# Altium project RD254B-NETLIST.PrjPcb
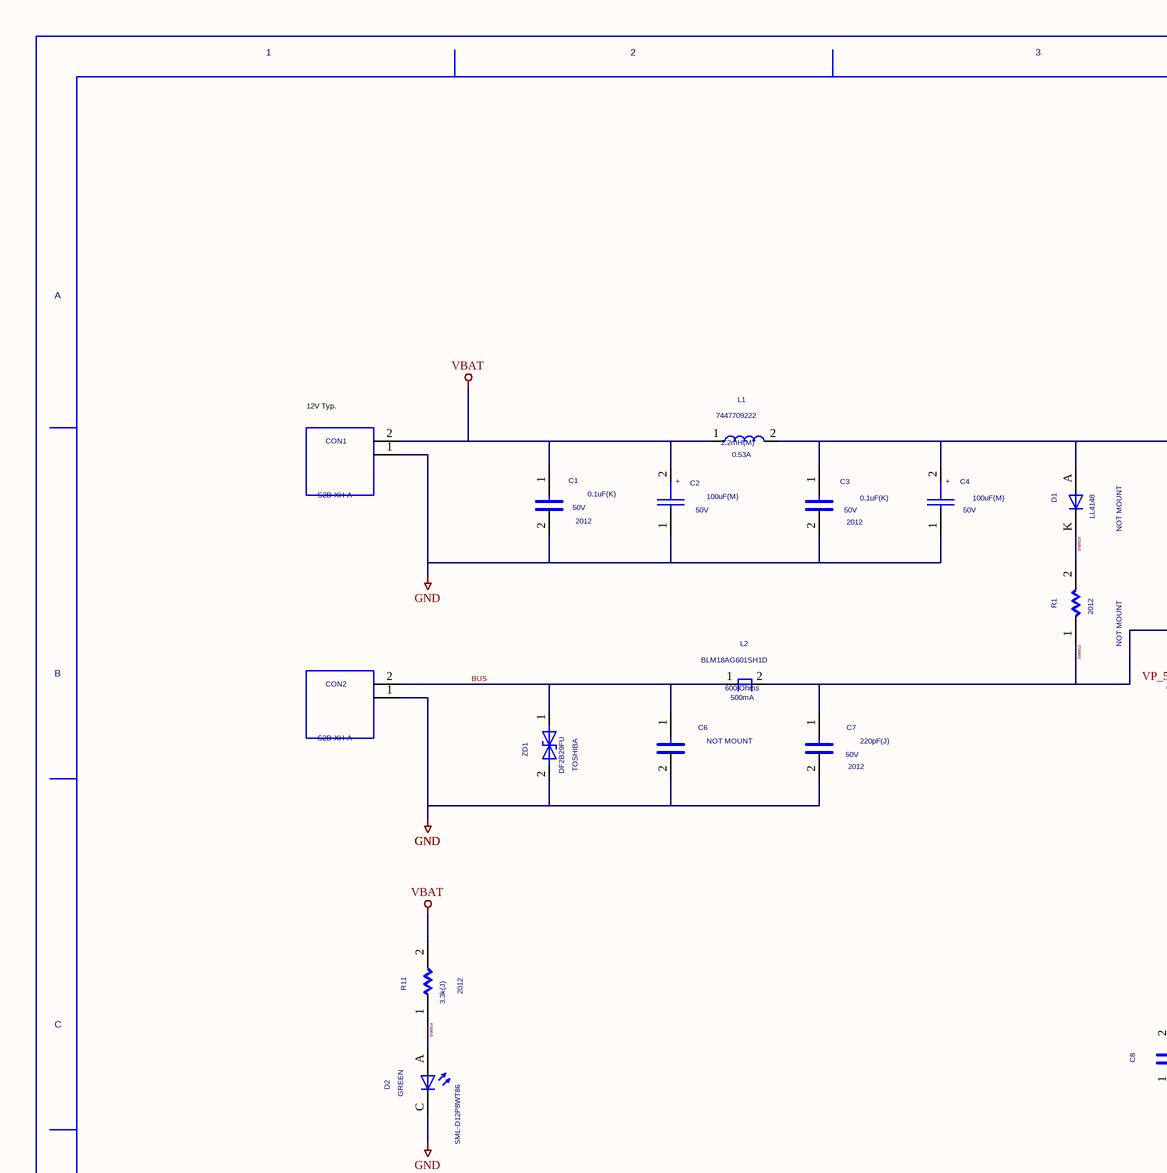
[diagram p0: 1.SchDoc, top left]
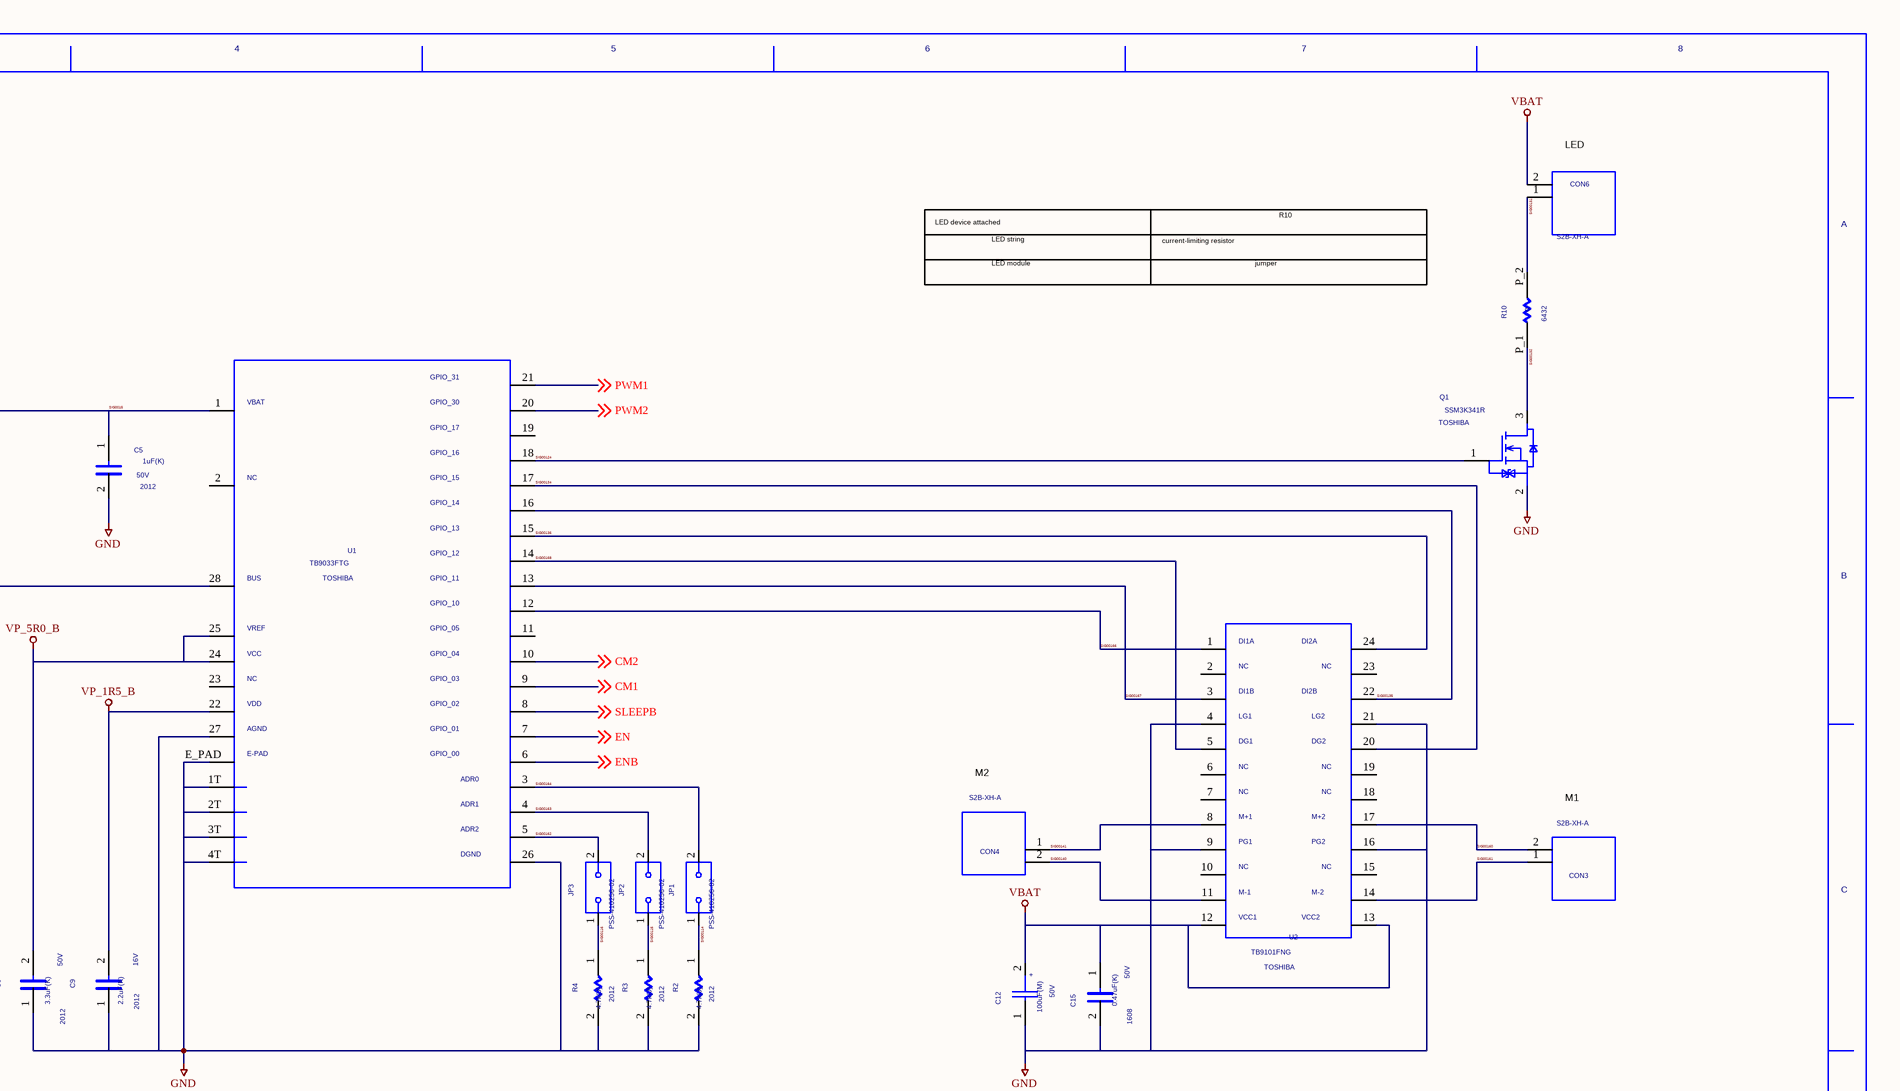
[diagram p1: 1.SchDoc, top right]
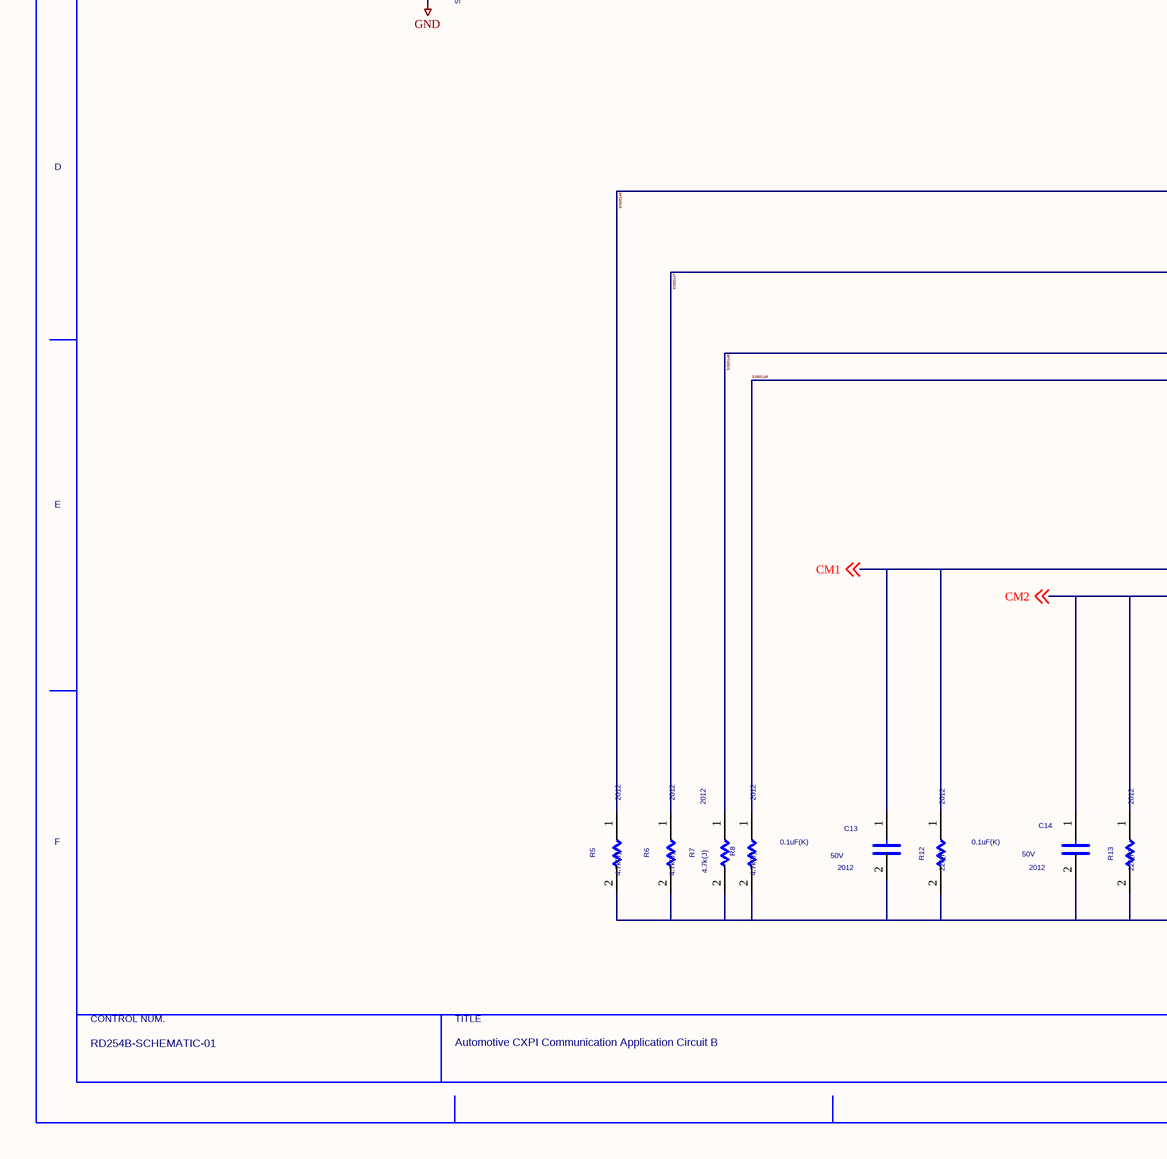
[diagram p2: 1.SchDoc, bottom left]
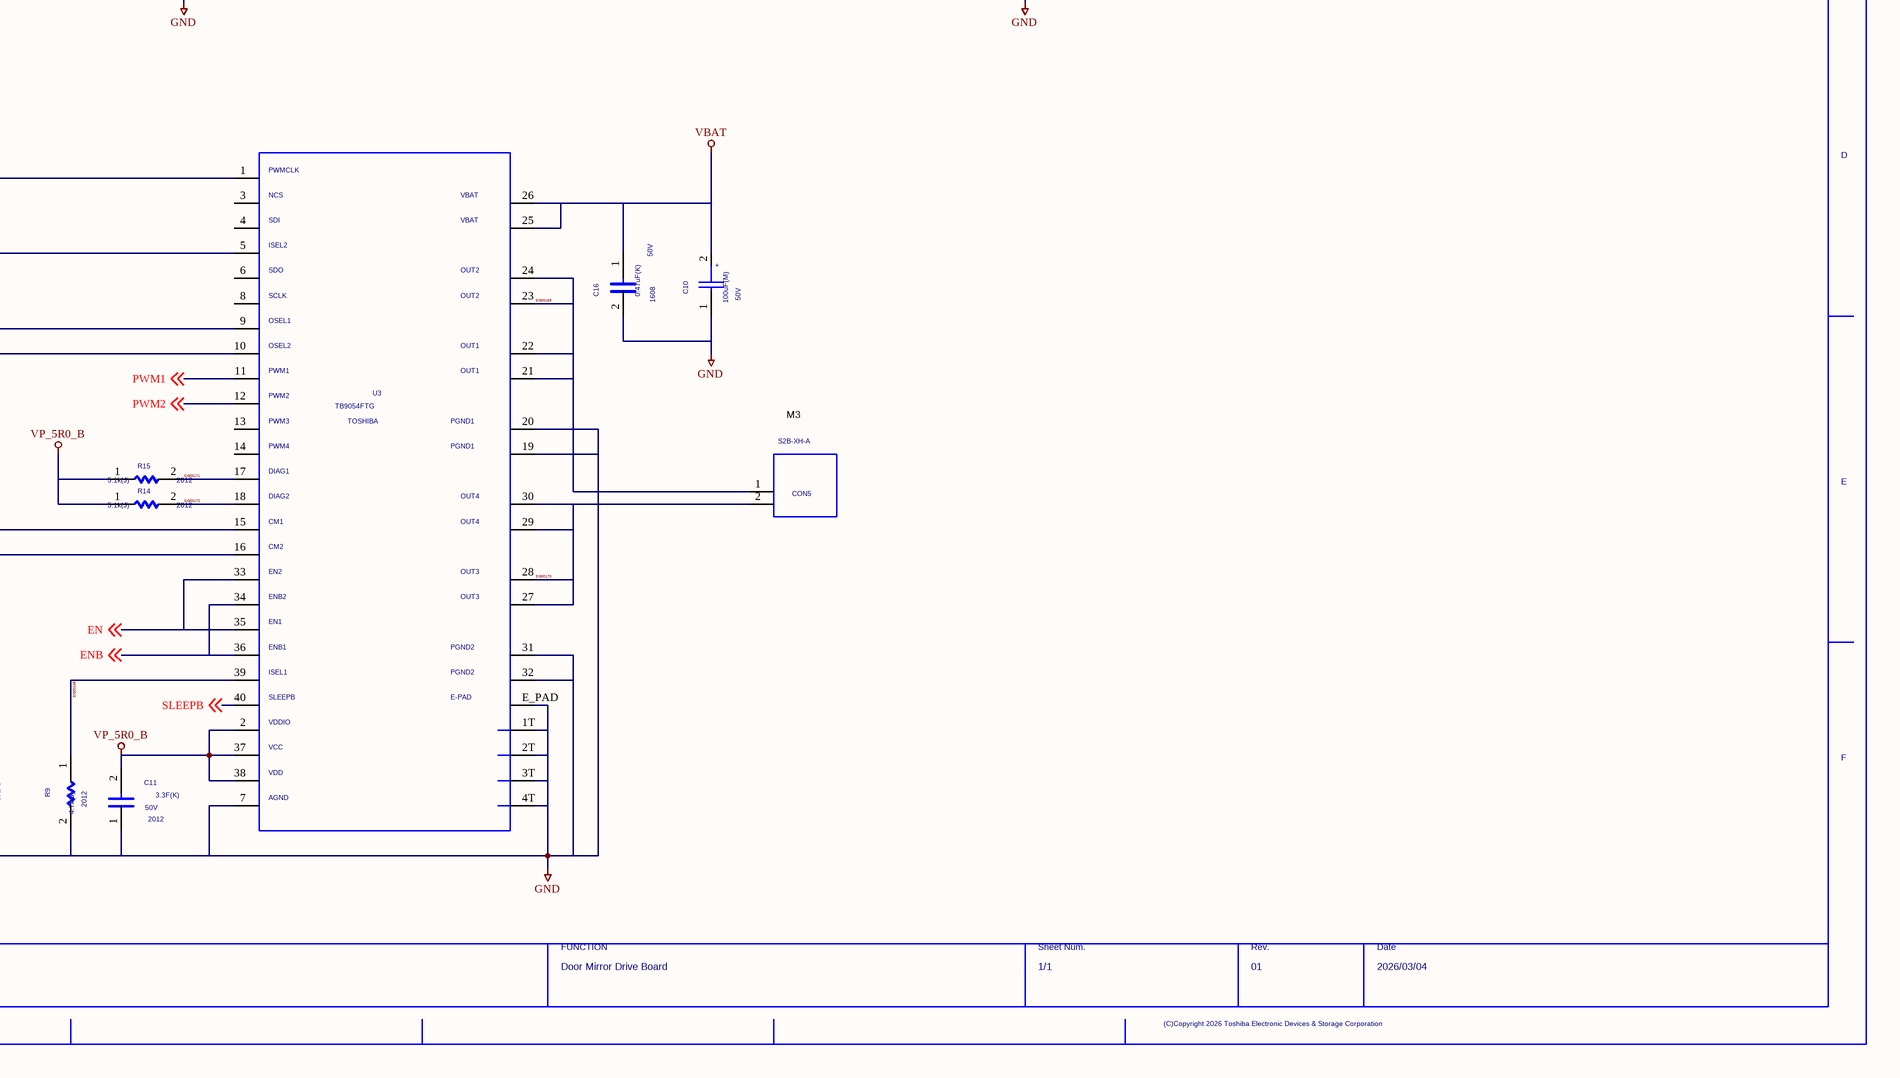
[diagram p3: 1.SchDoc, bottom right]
1 sheet, 50 parts. Net scope: global (net labels, ports and power ports of the same name join across sheets).

## Sheet 1.SchDoc
size 609 x 444 mm

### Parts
C1  VAL1: 0.1uF(K)  VAL2: 50V  SIZECODESMD: 2012  (hidden comment: C)
C2  VAL1: 100uF(M)  VAL2: 50V  (hidden comment: CP)
C3  VAL1: 0.1uF(K)  VAL2: 50V  SIZECODESMD: 2012  (hidden comment: C)
C4  VAL1: 100uF(M)  VAL2: 50V  (hidden comment: CP)
C5  VAL1: 1uF(K)  VAL2: 50V  SIZECODESMD: 2012  (hidden comment: C)
C6  NOTMOUNT: NOT MOUNT  (hidden comment: C)
C7  VAL1: 220pF(J)  VAL2: 50V  SIZECODESMD: 2012  (hidden comment: C)
C8  VAL1: 3.3uF(K)  VAL2: 50V  SIZECODESMD: 2012  (hidden comment: C)
C9  VAL1: 2.2uF(K)  VAL2: 16V  SIZECODESMD: 2012  (hidden comment: C)
C10  VAL1: 100uF(M)  VAL2: 50V  (hidden comment: CP)
C11  VAL1: 3.3F(K)  VAL2: 50V  SIZECODESMD: 2012  (hidden comment: C)
C12  VAL1: 100uF(M)  VAL2: 50V  (hidden comment: CP)
C13  VAL1: 0.1uF(K)  VAL2: 50V  SIZECODESMD: 2012  (hidden comment: C)
C14  VAL1: 0.1uF(K)  VAL2: 50V  SIZECODESMD: 2012  (hidden comment: C)
C15  VAL1: 0.47uF(K)  VAL2: 50V  SIZECODESMD: 1608  (hidden comment: C)
C16  VAL1: 0.47uF(K)  VAL2: 50V  SIZECODESMD: 1608  (hidden comment: C)
CON1  S2B-XH-A
CON2  S2B-XH-A
CON3  S2B-XH-A
CON4  S2B-XH-A
CON5  S2B-XH-A
CON6  S2B-XH-A
D1  NOTMOUNT: NOT MOUNT  VAL3: LL4148  (hidden comment: D)
D2  VAL2: GREEN  VAL3: SML-D12P8WT86  (hidden comment: LED)
JP1  PSS-410256-02
JP2  PSS-410256-02
JP3  PSS-410256-02
L1  VAL1: 2.2mH(M)  VAL2: 0.53A  VAL3: 7447709222  (hidden comment: L)
L2  VAL2: 500mA  VAL1: 600 Ohms  VAL3: BLM18AG601SH1D  (hidden comment: FB)
Q1  USERCOMPTEXT3: TOSHIBA  (hidden comment: SSM3K341R)
R1  NOTMOUNT: NOT MOUNT  SIZECODESMD: 2012  (hidden comment: R)
R2  VAL1: 4.7k(J)  SIZECODESMD: 2012  (hidden comment: R)
R3  VAL1: 4.7k(J)  SIZECODESMD: 2012  (hidden comment: R)
R4  VAL1: 4.7k(J)  SIZECODESMD: 2012  (hidden comment: R)
R5  VAL1: 4.7k(J)  SIZECODESMD: 2012  (hidden comment: R)
R6  VAL1: 4.7k(J)  SIZECODESMD: 2012  (hidden comment: R)
R7  VAL1: 4.7k(J)  SIZECODESMD: 2012  (hidden comment: R)
R8  VAL1: 4.7k(J)  SIZECODESMD: 2012  (hidden comment: R)
R9  VAL1: 4.7k(J)  SIZECODESMD: 2012  (hidden comment: R)
R10  VAL1: 0  SIZECODESMD: 6432  (hidden comment: R)
R11  VAL1: 3.3k(J)  SIZECODESMD: 2012  (hidden comment: R)
R12  VAL1: 220(F)  SIZECODESMD: 2012  (hidden comment: R)
R13  VAL1: 220(F)  SIZECODESMD: 2012  (hidden comment: R)
R14  VAL1: 5.1k(J)  SIZECODESMD: 2012  (hidden comment: R)
R15  VAL1: 5.1k(J)  SIZECODESMD: 2012  (hidden comment: R)
U1  VAL3: TB9033FTG  USERCOMPTEXT3: TOSHIBA  (hidden comment: TB9033FTGIC_VERB)
U2  USERCOMPTEXT3: TOSHIBA  (hidden comment: TB9101FNG)
U3  VAL3: TB9054FTG  USERCOMPTEXT3: TOSHIBA  (hidden comment: TB9054FTG_VERB)
U?  DATE: 2026/03/04  DRAWINGNUMBER: RD254B-SCHEMATIC-01  TITLE: Automotive CXPI Communication Application Circuit B  FUNCTION: Door Mirror Drive Board  SHEETNUMBER: 1/1  REVISION: 01  (hidden comment: WAKU_DEF_A3_1)
ZD1  USERCOMPTEXT3: TOSHIBA  VAL3: DF2B29FU  (hidden comment: ZDB)

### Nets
GND: C1.2 C2.1 C3.2 C4.1 C5.2 C6.2 C7.2 C8.1 C9.1 C10.1 C11.1 C12.1 C13.2 C14.2 C15.2 C16.2 CON1.1 CON2.1 D2.C Q1.2 R2.2 R3.2 R4.2 R5.2 R6.2 R7.2 R8.2 R9.2 R12.2 R13.2 U1.1T U1.2T U1.3T U1.4T U1.26 U1.27 U1.E_PAD U2.4 U2.9 U2.16 U2.21 U3.1T U3.2T U3.3T U3.4T U3.7 U3.19 U3.20 U3.31 U3.32 U3.E_PAD ZD1.2
VBAT: C1.1 C2.2 C10.2 C12.2 C15.1 C16.1 CON1.2 CON6.2 L1.1 R11.2 U2.12 U2.13 U3.25 U3.26
VP_1R5_B: C9.2 U1.22
VP_5R0_B: C8.2 C11.2 R14.1 R15.1 U1.24 U1.25 U3.2 U3.37 U3.38
BUS: C6.1 CON2.2 L2.1 ZD1.1
CM1: C13.1 R12.1 U1.9 U3.15 ; off-sheet CM1
CM2: C14.1 R13.1 U1.10 U3.16 ; off-sheet CM2
EN: U1.7 U3.33 U3.35 ; off-sheet EN
ENB: U1.6 U3.34 U3.36 ; off-sheet ENB
PWM1: U1.21 U3.11 ; off-sheet PWM1
PWM2: U1.20 U3.12 ; off-sheet PWM2
SIG0012: C7.1 L2.2 R1.1 U1.28
SIG0013: D1.K(C) R1.2
SIG0014: D2.A R11.1
SIG0015: C3.1 C4.2 C5.1 D1.A L1.2 U1.1
SIG00114: JP1.1 R2.1
SIG00115: JP2.1 R3.1
SIG00116: JP3.1 R4.1
SIG00124: Q1.1 U1.18
SIG00131: CON6.1 R10.P_2
SIG00132: Q1.3 R10.P_1
SIG00134: U1.17 U2.20
SIG00135: U1.16 U2.22
SIG00136: U1.15 U2.24
SIG00140: CON4.2 U2.11
SIG00141: CON4.1 U2.8
SIG00145: R9.1 U3.39
SIG00146: R5.1 U3.1
SIG00147: R6.1 U3.5
SIG00148: R7.1 U3.9
SIG00149: R8.1 U3.10
SIG00160: CON3.2 U2.17
SIG00161: CON3.1 U2.14
SIG00162: JP3.2 U1.5
SIG00163: JP2.2 U1.4
SIG00164: JP1.2 U1.3
SIG00166: U1.12 U2.1
SIG00167: U1.13 U2.3
SIG00168: U1.14 U2.5
SIG00169: CON5.1 U3.21 U3.22 U3.23 U3.24
SIG00170: CON5.2 U3.27 U3.28 U3.29 U3.30
SIG00171: R15.2 U3.17
SIG00172: R14.2 U3.18
SLEEPB: U1.8 U3.40 ; off-sheet SLEEPB

Not connected (* = marked no-connect by the designer): U1 2 11 19 23; U2 2 6 7 10 15 18 19 23; U3 3 4 6 8 13 14

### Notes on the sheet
- (near CON6) LED
- LED device attached
  to CON6
- LED string
- current-limiting resistor
- R10
- LED module
- jumper
- (near CON1) 12V Typ.
  6V to 16V
- M2
- (near CON3) M1
- M3

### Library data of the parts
C1 C3 C5-C7 C13-C16 = C: OriginalSymbolOrigin: (2540,7620); SAVECOUNT: 0
C2 C4 C10 C12 = CP: SAVEAREA0: -1450,-153,20294,13055; SAVECOUNT: 52; TIME: 15:02:55; UPDATEUSER: fukuda-y; UPDATETIME: 16:13:42; OriginalSymbolOrigin: (2540,10160); COMP: C
C8 C9 C11 = C#1: OriginalSymbolOrigin: (2540,7620); CaptureCellPackProp: C##1; SAVECOUNT: 0
CON1-CON6 = S2B-XH-A: SAVEAREA0: -63393,-16950,474261,314592; TIME: 14:30:25; UPDATEUSER: t5459927; UPDATETIME: 11:18:03; SAVECOUNT: 20; OriginalSymbolOrigin: (0,12700)
D1 = D: SAVEAREA0: -225,-91,12804,7836; SAVECOUNT: 3; TIME: 14:49:55; UPDATEUSER: 19870035; UPDATETIME: 14:20:16; OriginalSymbolOrigin: (5080,5080)
D2 = LED: SAVEAREA0: -6799,-183,19247,15664; TIME: 14:49:55; UPDATEUSER: fukuda-y; UPDATETIME: 13:54:07; SAVECOUNT: 4; OriginalSymbolOrigin: (5080,7620)
JP1-JP3 = PSS-410256-02: SAVEAREA0: -63393,-16950,474261,314592; TIME: 14:30:25; UPDATEUSER: t5459927; UPDATETIME: 18:56:33; SAVECOUNT: 22; OriginalSymbolOrigin: (2540,5080)
L1 = L: OriginalSymbolOrigin: (2540,5080); SAVECOUNT: 0
L2 = FB: SAVEAREA0: -63393,-16950,474261,314592; TIME: 14:30:25; UPDATEUSER: t5459927; UPDATETIME: 11:02:03; SAVECOUNT: 20; OriginalSymbolOrigin: (7620,7620)
Q1 = SSM3K341R: SAVEAREA0: -63393,-16950,474261,314592; TIME: 14:30:25; UPDATEUSER: t5459927; UPDATETIME: 12:01:19; SAVECOUNT: 22; OriginalSymbolOrigin: (5080,12700)
R1 = R: VAL2: 250mW; VAL1: 1k(J); OriginalSymbolOrigin: (5080,5080); SAVECOUNT: 0
R2-R9 R12-R15 = R: VAL2: 250mW; OriginalSymbolOrigin: (5080,5080); SAVECOUNT: 0
R10 = R#2: VAL2: 2W; OriginalSymbolOrigin: (5080,5080); CaptureCellPackProp: R##2
R11 = R#1: VAL2: 250mW; OriginalSymbolOrigin: (5080,5080); CaptureCellPackProp: R##1; SAVECOUNT: 0
U1 = TB9033FTGIC_VERB: SAVEAREA0: -63393,-16950,474261,314592; TIME: 14:30:25; UPDATEUSER: t5459927; UPDATETIME: 17:47:26; SAVECOUNT: 27; OriginalSymbolOrigin: (5080,106680)
U2 = TB9101FNG: SAVEAREA0: -63393,-16950,474261,314592; TIME: 14:30:25; UPDATEUSER: t5459927; UPDATETIME: 15:25:03; SAVECOUNT: 19; OriginalSymbolOrigin: (5080,63500)
U3 = TB9054FTG_VERB: SAVEAREA0: -63393,-16950,474261,314592; TIME: 14:30:25; UPDATEUSER: t5459927; UPDATETIME: 17:43:58; SAVECOUNT: 30; OriginalSymbolOrigin: (5080,137160)
U? = WAKU_DEF_A3_1: PLOTTIME: HH:MM; SAVEAREA0: 96913,-567914,509243,-368858; TIME: 16:57:06; UPDATEUSER: t5459927; UPDATETIME: 10:24:54; SAVECOUNT: 4; ZONEOFFSETX: 36; ZONEOFFSETY: -24; OriginalSymbolOrigin: (12700,-12700); SHTSAVECOUNT: 71
ZD1 = ZDB: SAVEAREA0: -4630,-153,17114,13055; TIME: 14:49:55; UPDATEUSER: fukuda-y; UPDATETIME: 08:22:19; SAVECOUNT: 6; OriginalSymbolOrigin: (2540,5080)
